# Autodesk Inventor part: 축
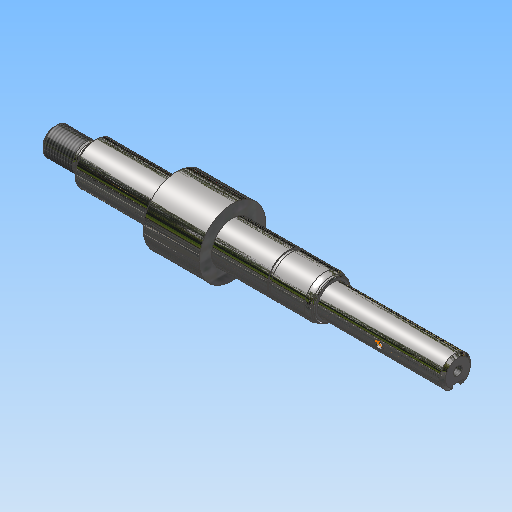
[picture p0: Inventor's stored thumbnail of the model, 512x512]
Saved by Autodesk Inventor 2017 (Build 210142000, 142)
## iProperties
Created: 2016-08
Part Number: 축
Material: 강철, 탄소
Document SubType Name: Modeling
Designer: mduedu
Density: 7.87 g/cm^3
Appearance: 반광택
Author: mduedu
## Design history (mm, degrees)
sketch "스케치1"
  geometry: L1 (-72.5, 0)-(72.5, 0); L2 (-72.5, 0)-(-72.5, 5); L3 (-72.5, 5)-(-58.5, 5); L4 (-58.5, 5)-(-58.5, 7.5); L5 (-58.5, 7.5)-(25.855, 7.5); L6 (27.5, 6.55)-(27.5, 5.5); L7 (27.5, 5.5)-(72.5, 5.5); L8 (72.5, 5.5)-(72.5, 0); L9 (27.5, 6.55)-(25.855, 7.5); 2 further points
  constraints: 18 end point, 5 parallel, 2 perpendicular, 1 coincident, 1 horizontal, 1 midpoint
  dimensions: "d0" = 145 distance of L1.start L1.end; "d2" = 14 distance of L2.end L3.end; "d4" = 10 diameter of L3 L1; "d5" = 15 diameter of L5 L1; "d6" = 11 diameter of L7 L1; "d63" = 45 distance between parallel lines of L6 L8; "d64" = 30 deg angle of L5 L9; "d65" = 13.1 diameter of L6.start L1
revolve "회전1" sketch "스케치1" stored, may be unused: angle "d7" = 90 deg
sketch "스케치2"
  geometry: L1 (-58.5, -5)-(-58.5, 5) reference; L2 (72.5, -5.5)-(72.5, 5.5) reference; L3 (-58.5, 0)-(72.5, 0); L4 (-60.5, 4.5)-(-60.5, 5); L5 (-60.5, 5)-(-58.5, 5); L6 (-58.5, 5)-(-58.5, 4.5); L7 (-60.5, 4.5)-(-58.5, 4.5); 1 further point
  constraints: 10 end point, 2 midpoint, 1 parallel, 1 perpendicular, 1 point on line
  dimensions: "d8" = 2 distance of L4.end L5.end; "d10" = 10 diameter of L5 L3; "d11" = 9 diameter of L7 L3
revolve "회전2" sketch "스케치2" stored, may be unused: angle "d12" = 90 deg
node "작업 평면1"
sketch "스케치3"
  geometry: C1 r 12 at (0, 0); 1 further point
  constraints: 1 centre point, 1 coincident
  dimensions: "d15" = 24 diameter of C1
extrude "돌출1" join sketch "스케치3" distance "d16" = 20; taper "d17" = 0 deg
sketch "스케치5"
  geometry: L1 (-72.5, -5)-(-72.5, 5) reference; L2 (72.5, -5.5)-(72.5, 5.5) reference; L3 (-72.5, 0)-(72.5, 0); L4 (-8.5, 7.5)-(25.855, 7.5) reference; L5 (12.65, 7.5)-(11.5, 7.5); L6 (11.5, 7.5)-(11.5, 7.15); L7 (11.5, 7.15)-(12.65, 7.15); L8 (12.65, 7.15)-(12.65, 7.5); L9 (-8.5, -12)-(-8.5, 12) reference; 1 further point
  constraints: 10 end point, 2 midpoint, 2 parallel, 1 horizontal, 1 perpendicular, 1 point on line
  dimensions: "d20" = 1.15 distance between parallel lines of L8 L6; "d21" = 14.3 diameter of L7 L3; "d82" = 20 distance between parallel lines of L9 L6
revolve "회전3" sketch "스케치5" stored, may be unused: angle "d22" = 90 deg
node "작업 평면3"
sketch "스케치6"
  geometry: L1 (-6.5, 2)-(-22.5, 2); L2 (-22.5, 2)-(-22.5, -2); L3 (-22.5, -2)-(-6.5, -2); L4 (-22.5, 5.5)-(-22.5, -5.5) reference; A1 r 2 centre (-6.5, 0) between (-6.5, -2) and (-6.5, 2); 2 further points
  constraints: 6 end point, 2 midpoint, 2 point on circle, 2 tangent, 1 centre point, 1 horizontal, 1 horizontal alignment, 1 parallel, 1 perpendicular
  dimensions: "d23" = 4 distance between parallel lines of L3 L1; "d62" = 18 dimension on A1 L2
extrude "돌출2" cut sketch "스케치6" distance "d25" = 2.5; taper "d26" = 0 deg
feature "스레드1" dims "d27" = 10, "d28" = 0
chamfer "모따기5" distance "d41" = 0.5; stored, may be unused: second distance "d42" = 2, angle "d43" = 45 deg
chamfer "모따기7" distance "d47" = 1; stored, may be unused: second distance "d48" = 2, angle "d49" = 45 deg
chamfer "모따기8" distance "d50" = 1; stored, may be unused: second distance "d51" = 2, angle "d52" = 45 deg
sketch "스케치8"
  geometry: 1 further point
hole "구멍1" sketch "스케치8" at (2, 3.5) diameter "d53" = 3.242; stored, may be unused: countersink angle "d57" = 90 deg, drill point angle "d59" = 120 deg; dims "d54" = 10, "d55" = 4, "d56" = 2, "d58" = 12
fillet "모깎기1" dims "d66" = 4, "d67" = 0.5
sketch "스케치10"
  geometry: L1 (-27.5, 5.5)-(-71.5, 5.5) reference; L2 (-51, 5.5)-(-49.5, 4); L3 (-49.5, 4)-(-49.5, 5.5); L4 (-72.5, -4.5)-(-72.5, 4.5) reference; 3 further points
  constraints: 4 end point, 1 midpoint, 1 perpendicular, 1 point on line
  dimensions: "d77" = 45 deg angle of L2 L3; "d78" = 3 diameter of L2.start L3; "d80" = 23 distance between parallel lines of L4 L3
revolve "회전4" sketch "스케치10" stored, may be unused: angle "d81" = 90 deg
node "작업점1"
node "솔리드1"
other parameters: "d13" = -44
